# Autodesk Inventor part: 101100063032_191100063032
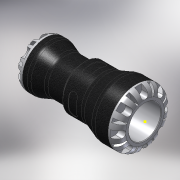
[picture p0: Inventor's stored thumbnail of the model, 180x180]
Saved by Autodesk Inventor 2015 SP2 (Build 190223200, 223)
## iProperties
Created: 2016-12
Part Number: 101100063032_191100063032
Material: PVC-Piping
Description: PLASSON REDUCING COUPLING 63X32 SERIES 1
Document SubType Name: Modeling
Designer: KIM
Mass: 602.108 g
Surface Area: 808.095 cm^2
Volume: 430.077 cm^3
Density: 1.4 g/cm^3
Appearance: Black Cast
Author: KIM
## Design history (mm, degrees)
derived "1011.ipt"
feature "Solid1::1011.ipt"
tag "TaggingFeature1"
body "Solid1"
other parameters: "d0" = 172, "d2" = 38.22, "d3" = 63, "d4" = 103, "d5" = 75.6, "d6" = 91, "d7" = 5.25, "d8" = 58, "d9" = 32, "d11" = 23.1, "d12" = 55, "d13" = 2.66667, "d14" = 82.4, "d15" = 46.4, "d16" = 20 deg, "d17" = 20 deg, "d18" = 130 deg, "d22" = 10.96, "d25" = 10.96, "d26" = 0, "d28" = 360 deg, "d30" = 8 deg, "d31" = 1.26, "d32" = 8 deg, "d33" = 1.26, "d35" = 0, "d37" = 360 deg, "d39" = 7.2, "d42" = 7.2, "d43" = 0, "d45" = 360 deg, "d47" = 0.64, "d48" = 8 deg, "d49" = 8 deg, "d50" = 0.64, "d52" = 0, "d54" = 360 deg, "d56" = 11.6, "d57" = 20.6, "d58" = 0.5, "d60" = 12.36, "d61" = 15.75, "d62" = 17.46, "d63" = 0, "d66" = 0, "d68" = 360 deg, "d75" = 9.25585, "d77" = 80.34, "d78" = 1.03, "d_" = 63, "d1" = 32, "E_" = 103, "H_" = 172, "l_" = 91, "E1" = 58, "l1" = 55, "Plasson" = 1, "d20" = 9, "d21" = 13.7, "d23" = 103, "d24" = 75.6, "d40" = 58, "d59" = 18.5117
